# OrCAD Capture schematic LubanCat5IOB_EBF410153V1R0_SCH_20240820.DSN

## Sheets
1 17 MIPI DSI: size A4; title: 野火鲁班猫5.BTB底板; rev: V1.0; note: MIPI DSI接口; note: https://yehuosm.tmall.com
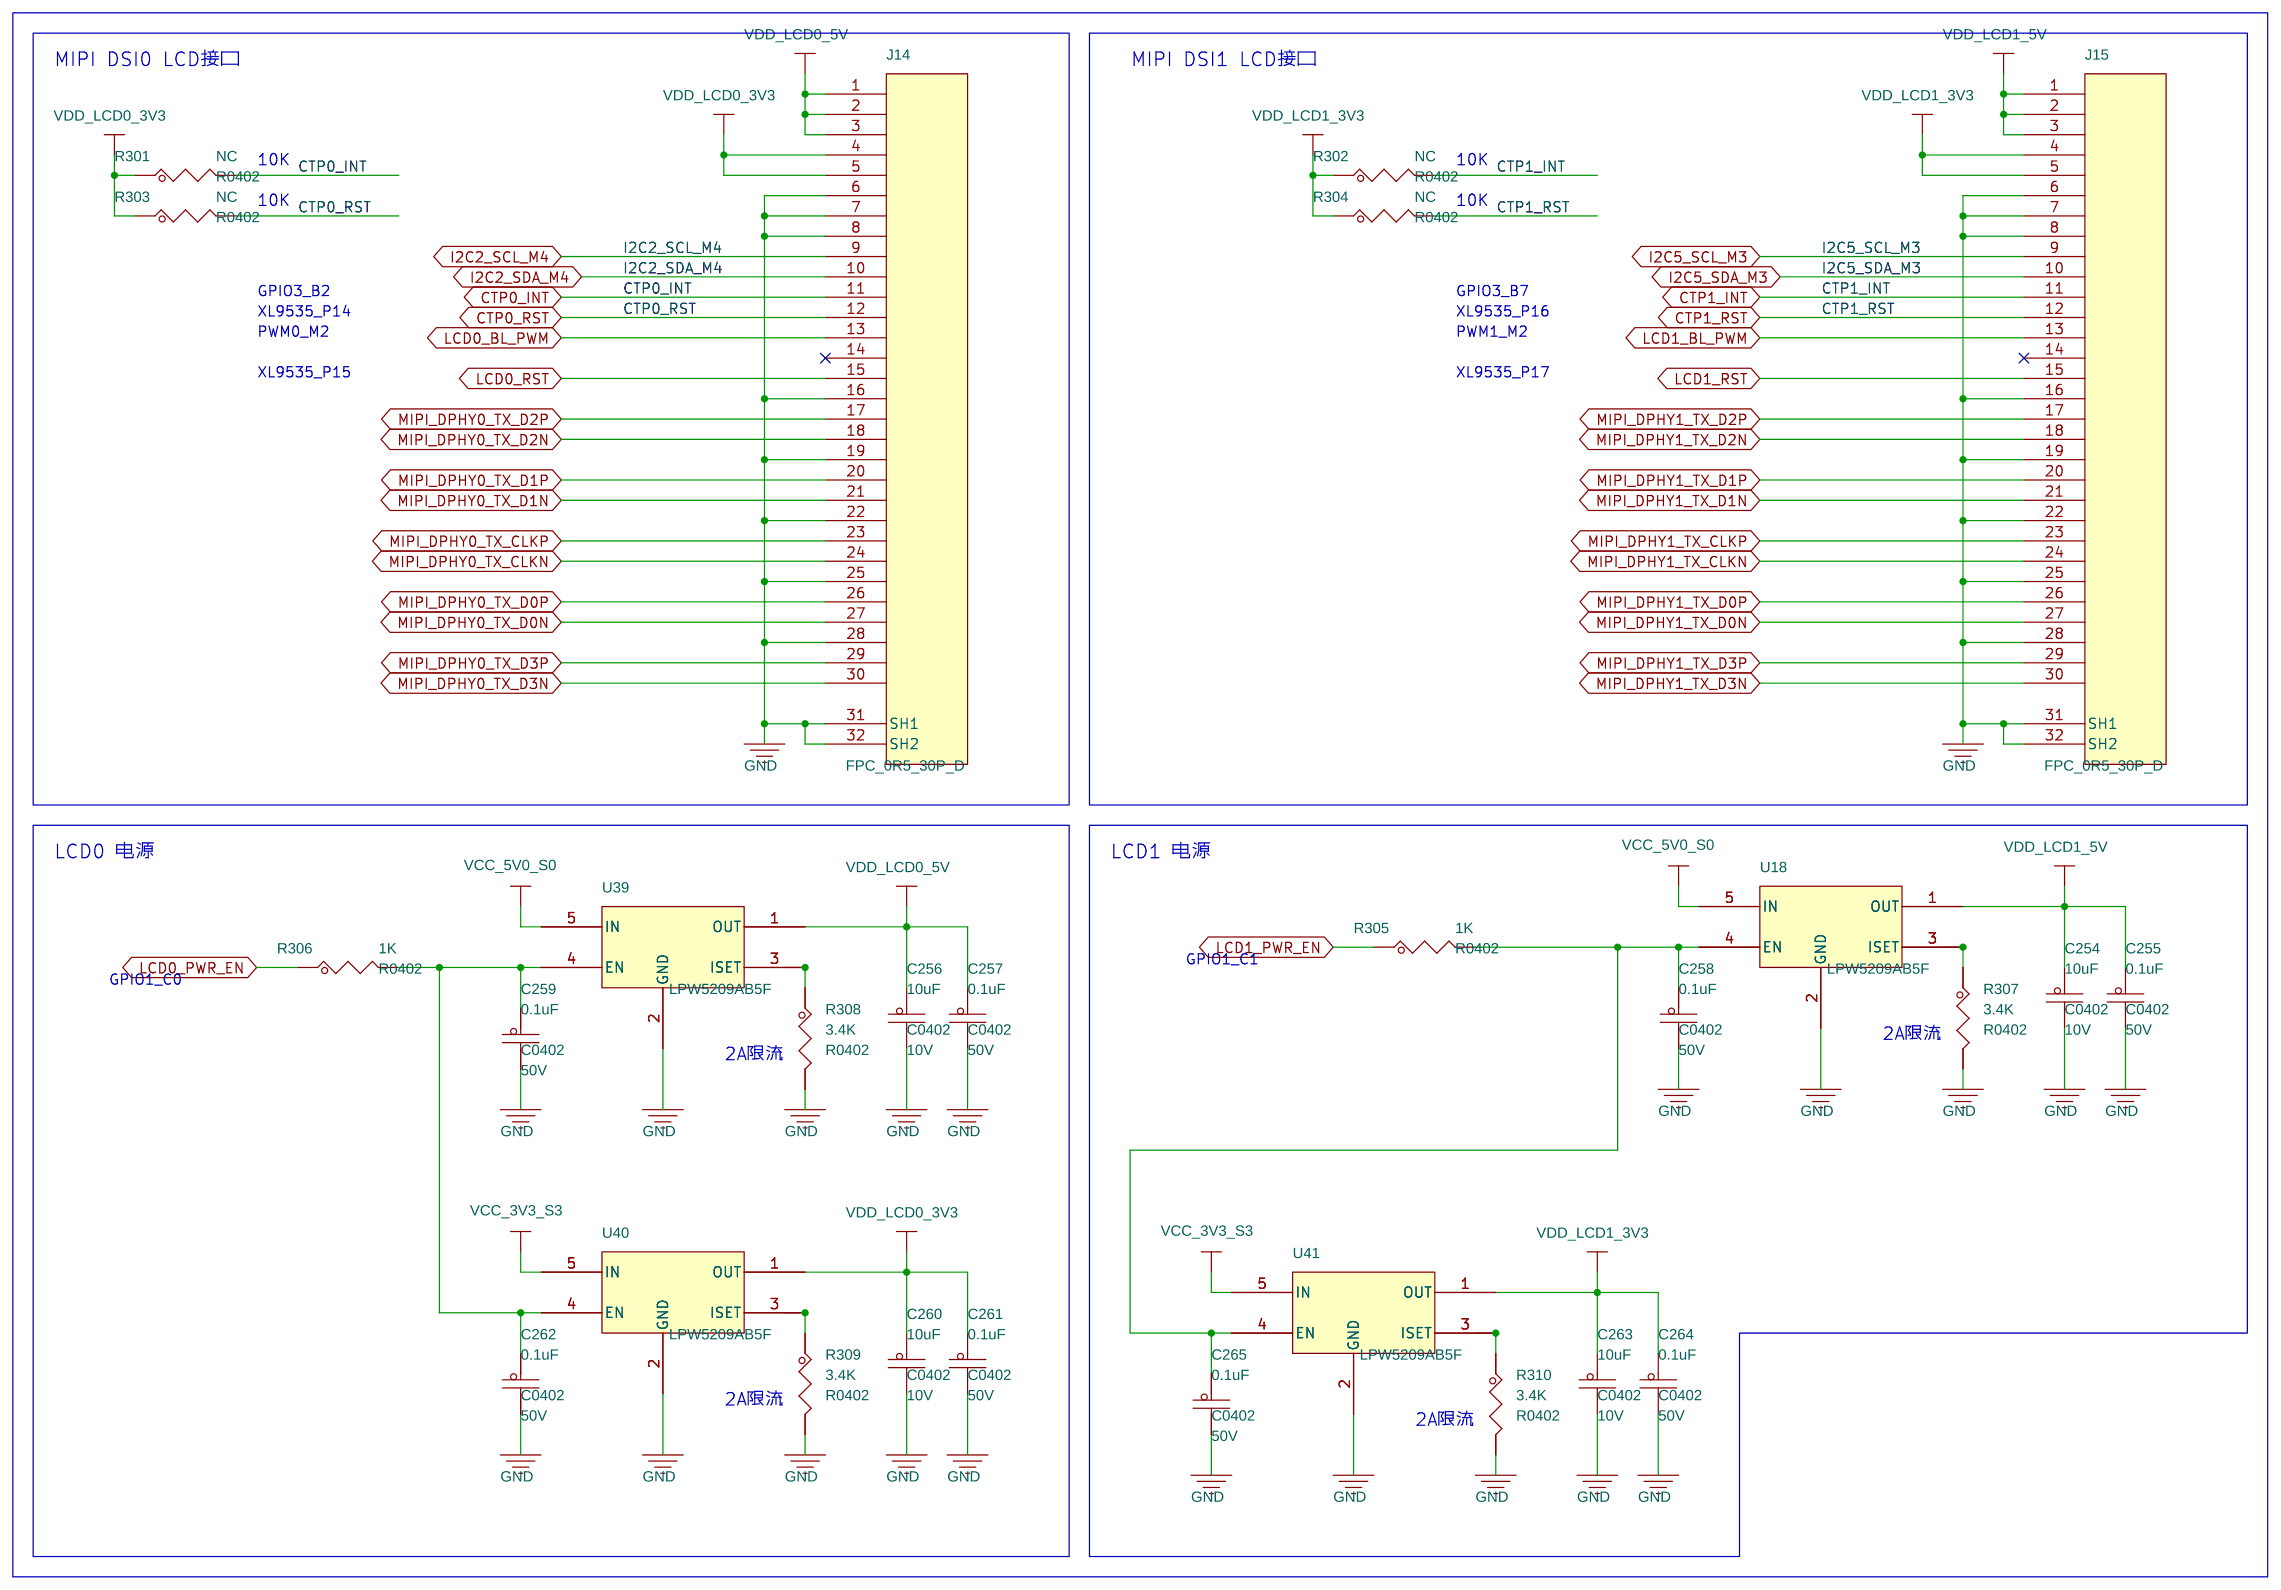
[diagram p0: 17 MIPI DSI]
2 06 RS232/RS485/CAN: size A4; note: RS232/RS485/CAN
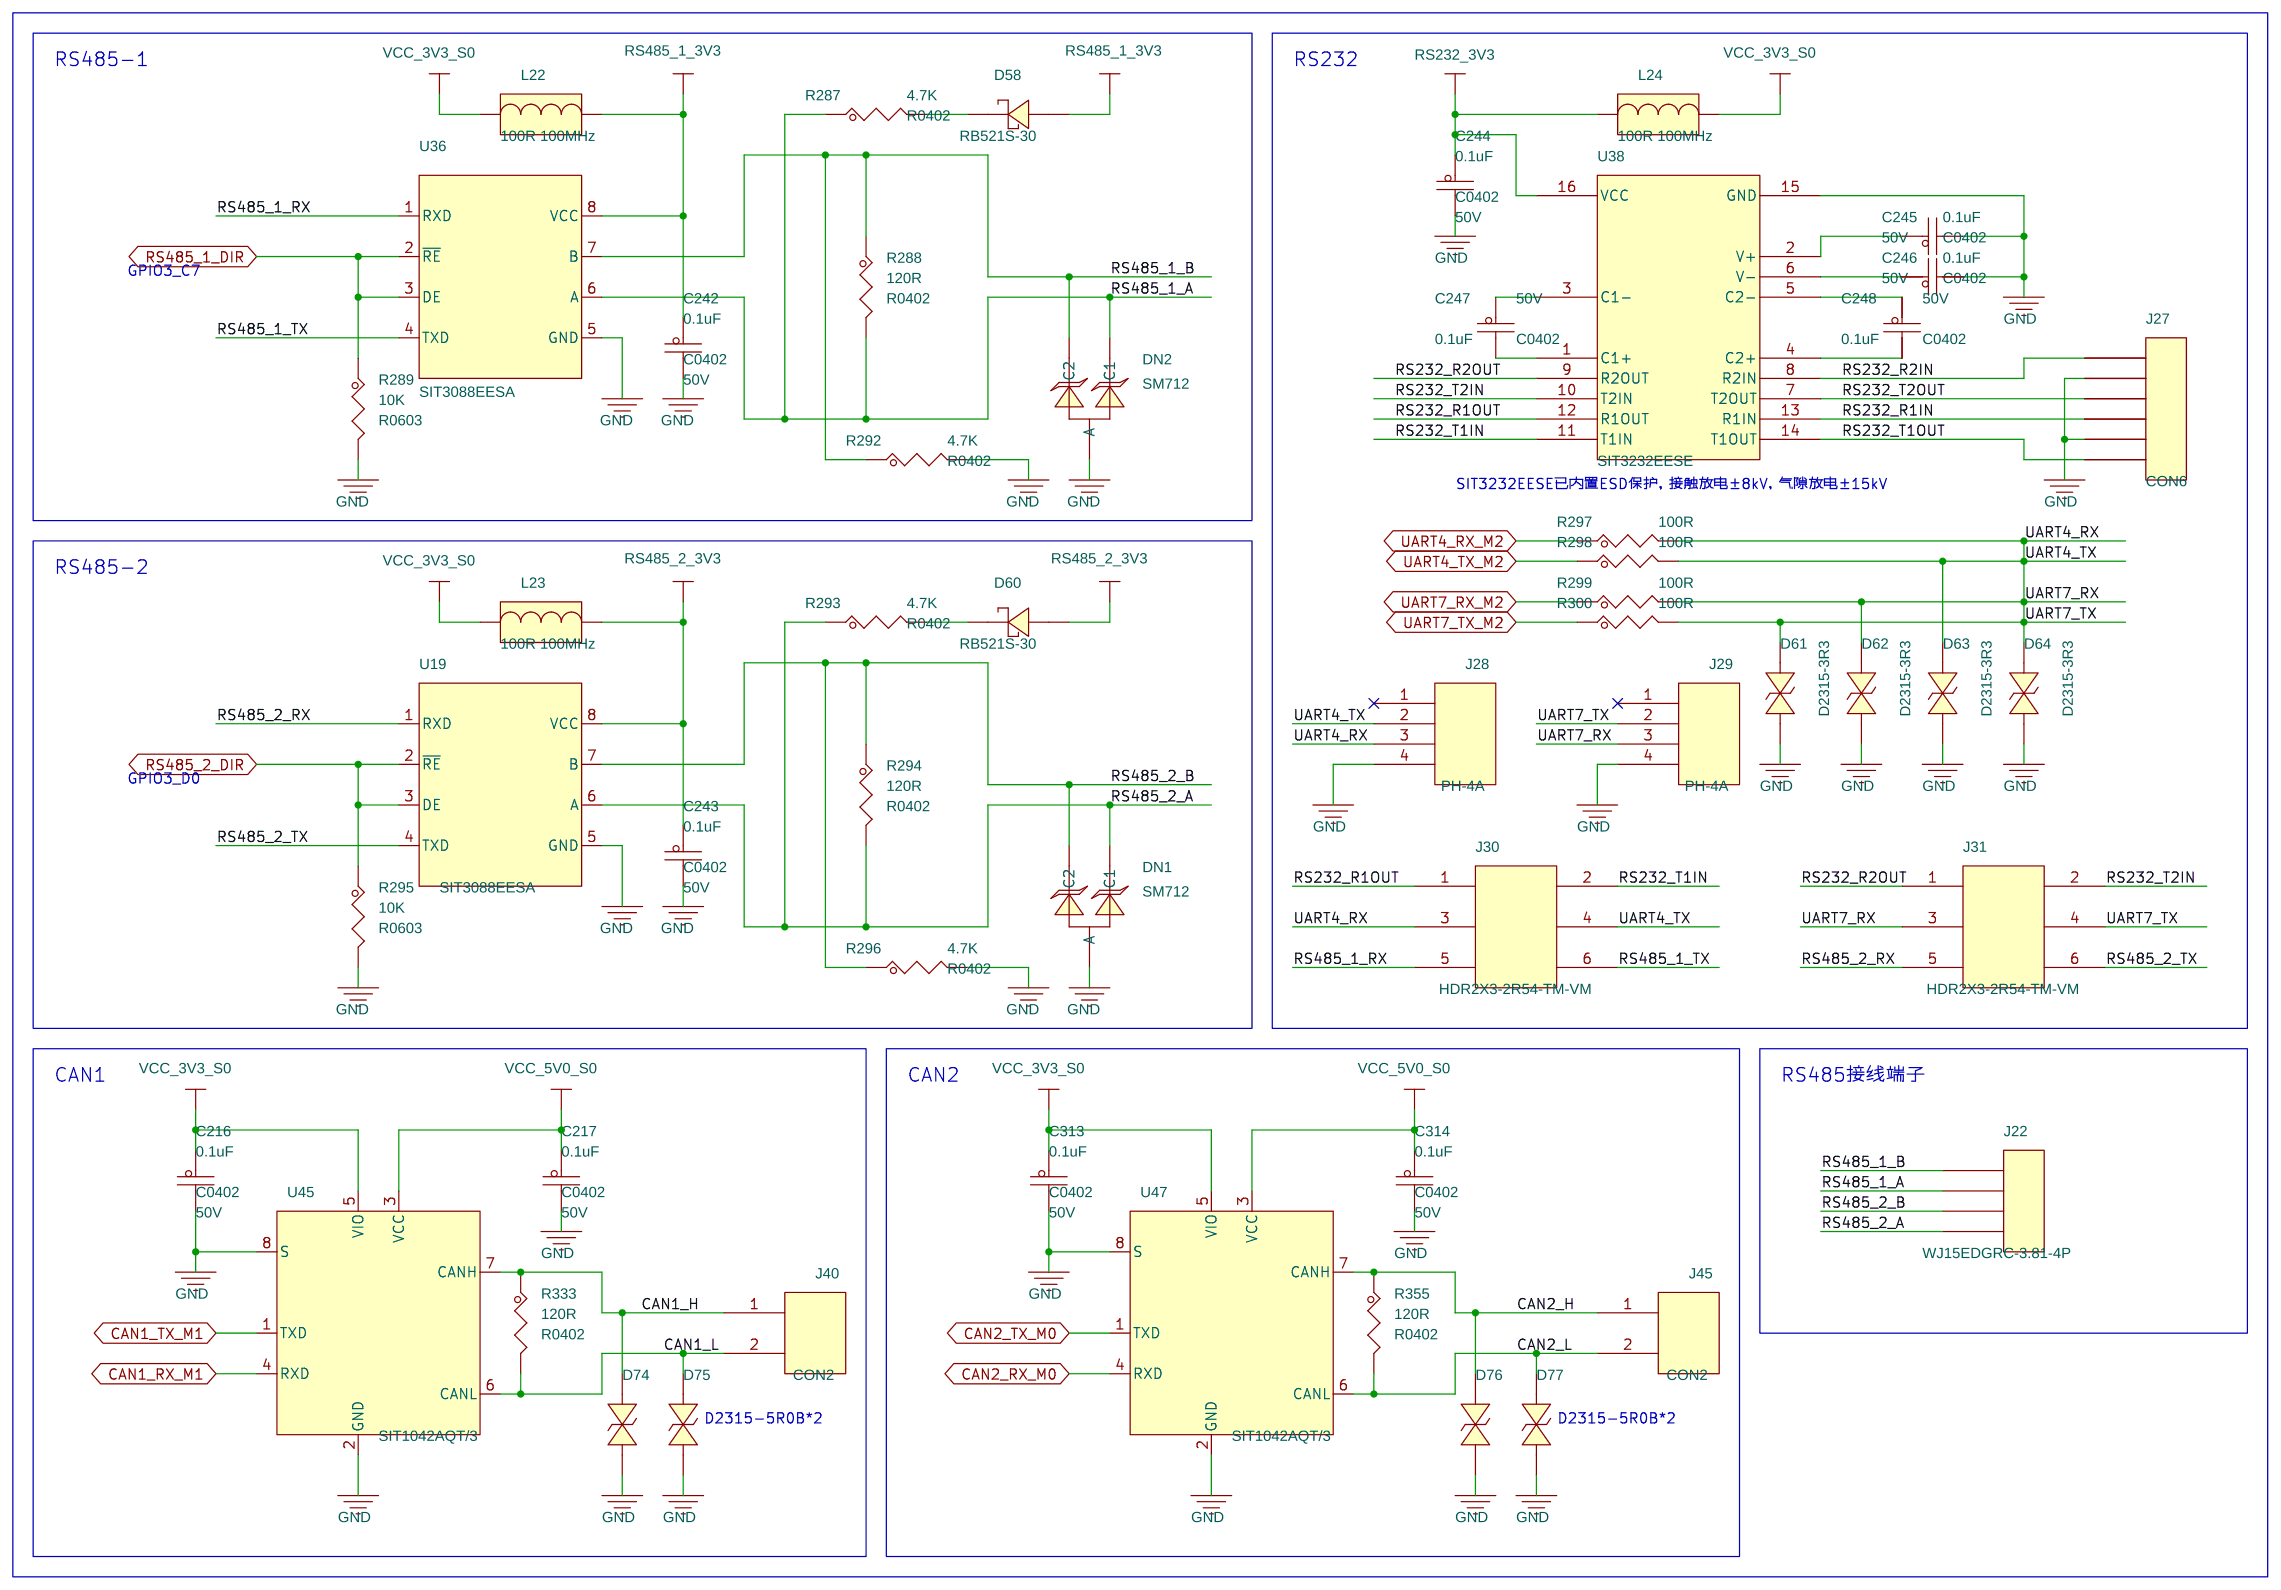
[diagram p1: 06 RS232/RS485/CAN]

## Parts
sheet 06 RS232/RS485/CAN
C216  0.1uF  [C0402]
C217  0.1uF  [C0402]
C242  0.1uF  [C0402]
C243  0.1uF  [C0402]
C244  0.1uF  [C0402]
C245  0.1uF  [C0402]
C246  0.1uF  [C0402]
C247  0.1uF  [C0402]
C248  0.1uF  [C0402]
C313  0.1uF  [C0402]
C314  0.1uF  [C0402]
D58  RB521S-30  [SOD523]
D60  RB521S-30  [SOD523]
D61  D2315-3R3  [esd0402]
D62  D2315-3R3  [esd0402]
D63  D2315-3R3  [esd0402]
D64  D2315-3R3  [esd0402]
D74  D2315-5R0B  [esd0402]
D75  D2315-5R0B  [esd0402]
D76  D2315-5R0B  [esd0402]
D77  D2315-5R0B  [esd0402]
DN1  SM712  [SOT23]
DN2  SM712  [SOT23]
J22  WJ15EDGRC-3.81-4P  [DB2ERC-3P81-4P]
J27  CON6  [DB2ERC-3P81-6P]
J28  PH-4A  [PH-1X4-2P0]
J29  PH-4A  [PH-1X4-2P0]
J30  HDR2X3-2R54-TM-VM  [HDR2X3-2R54-TM-VM]
J31  HDR2X3-2R54-TM-VM  [HDR2X3-2R54-TM-VM]
J40  CON2  [db2erc-3p81-2p]
J45  CON2  [db2erc-3p81-2p]
L22  100R 100MHz  [L0603]
L23  100R 100MHz  [L0603]
L24  100R 100MHz  [L0603]
R287  4.7K  [R0402]
R288  120R  [R0402]
R289  10K  [R0603]
R292  4.7K  [R0402]
R293  4.7K  [R0402]
R294  120R  [R0402]
R295  10K  [R0603]
R296  4.7K  [R0402]
R297  100R  [R0402]
R298  100R  [R0402]
R299  100R  [R0402]
R300  100R  [R0402]
R333  120R  [R0402]
R355  120R  [R0402]
U19  SIT3088EESA  [SOP8]
U36  SIT3088EESA  [SOP8]
U38  SIT3232EESE  [SOIC16]
U45  SIT1042AQT/3  [SOP8]
U47  SIT1042AQT/3  [SOP8]
sheet 17 MIPI DSI
C254  10uF  [C0402]
C255  0.1uF  [C0402]
C256  10uF  [C0402]
C257  0.1uF  [C0402]
C258  0.1uF  [C0402]
C259  0.1uF  [C0402]
C260  10uF  [C0402]
C261  0.1uF  [C0402]
C262  0.1uF  [C0402]
C263  10uF  [C0402]
C264  0.1uF  [C0402]
C265  0.1uF  [C0402]
J14  FPC_0R5_30P_D  [FPC-30P-0P5]
J15  FPC_0R5_30P_D  [FPC-30P-0P5]
R301  NC  [R0402]
R302  NC  [R0402]
R303  NC  [R0402]
R304  NC  [R0402]
R305  1K  [R0402]
R306  1K  [R0402]
R307  3.4K  [R0402]
R308  3.4K  [R0402]
R309  3.4K  [R0402]
R310  3.4K  [R0402]
U18  LPW5209AB5F  [SOT23-5]
U39  LPW5209AB5F  [SOT23-5]
U40  LPW5209AB5F  [SOT23-5]
U41  LPW5209AB5F  [SOT23-5]

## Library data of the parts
C216 C217 C242-C248 C255 C257-C259 C261 C262 C264 C265 C313 C314 = CAP_NP: Voltage: 50V; 规格: 贴片电容0.1uF 10% 50V X5R 0402; 规格编号: 0402X104K500NT; 规格书: 风华电容.pdf; 价格: 0.029826; 类别: 贴片电容0402; 品牌: 风华; 生命周期: 量产; 条码: EBF29060118
D58 D60 = DIODE_SCHTKY: 规格: 直流反向耐压(Vr)：30V 平均整流电流(Io)：200mA 正向压降(Vf)：500mV@200mA 30V@100mA,VF=350mV@10mA; 规格书: 江苏长电_RB521S-30.pdf; 价格: 0.06781; 类别: 贴片肖特基二极管; 品牌: 江苏长电; 生命周期: 量产; 条码: EBFCIS221114153437
D61-D64 = DIODE_BI-DIR_TRIG: 备注: 通用; 规格: 防静电保护ESD二极管 反向工作电压3.3V 击穿电压3.5V 钳位电压9V 结电容Cj 10pF; 规格书: 千虹_D2315-3R3.pdf; 类别: 贴片ESD; 品牌: 千虹; 生命周期: 量产; 条码: EBFCIS240517170749
D74-D77 = DIODE_BI-DIR_TRIG: 备注: 通用; 规格: 防静电保护ESD二极管 反向工作电压5V 击穿电压7V 钳位电压10.5V 结电容Cj 0.3pF; 规格书: 千虹_D2315-5R0B.pdf; 类别: 贴片ESD; 品牌: 千虹; 生命周期: 量产; 条码: EBFCIS240517170922
DN1 DN2 = TVS_Arr_ComA: 规格: 防静电保护ESD二极管 箝位电压12V -7V 击穿电压13.3V -7.5V; 规格书: 时科_SM712.pdf; 价格: 0.273512; 类别: 贴片ESD; 品牌: 时科; 生命周期: 量产; 条码: EBFCIS221015085507
J22 = CON4: 规格: 插拔式接线端子 间距3.81mm 90度弯针 4PIN; 规格书: 康奈克斯电气-绿色端子弯针插座.pdf; 价格: 0.198381; 类别: 绿色插拔式接线端子; 品牌: 康奈克斯电气; 生命周期: 量产; 条码: EBF29040009
J27 = CON6: 规格: 绿色插拔式接线端子 间距3.81mm 90度弯针 6PIN; 规格编号: WJ15EDGRC-3.81-6P; 规格书: 康奈克斯电气-绿色端子弯针插座.pdf; 价格: 0.301748; 类别: 绿色插拔式接线端子; 品牌: 康奈克斯电气; 生命周期: 量产; 条码: EBF29040013
J28 J29 = 1X4PIN: 规格: 直针PH2.0-4P 间距2.0MM 拔插式 接插件; 规格书: 博穆精密-PH2.0.pdf; 价格: 0.017; 可替代料: EBF29020025; 类别: PH连接器; 品牌: 博穆精密; 生命周期: 量产; 条码: EBF29020025
J30 J31 = 2X3PIN: 规格: 蓝色直插双排排针 总PIN数6 间距2.54mm; 规格编号: HDR2X3-2R54-TM-VM-BLUE; 规格书: 州日_双排针_直插_2P54.pdf; 类别: 2.54mm直插双排排针; 品牌: 州日; 生命周期: 量产; 条码: EBF29020030
J40 J45 = CON2: 规格: 绿色插拔式接线端子母座_2Pin  90度弯针 3.81间距; 规格编号: WJ15EDGRC-3.81-2P; 规格书: C8387_插针_板端弯针2P3.81MM_2019-12-25 .pdf; 价格: 0.107525; 类别: 绿色插拔式接线端子; 品牌: 康奈克斯电气; 生命周期: 量产; 条码: EBF29040070
L22-L24 = BEAD: 规格: 磁珠100Ω @100MHz 额定电流3A 直流电阻30mΩ; 规格编号: UPZ1608E101-3R0TF; 规格书: 顺络-磁珠.pdf; 价格: 0.021567; 类别: 贴片磁珠0603; 品牌: 顺络; 生命周期: 量产; 条码: EBF29050038
R287 R292 R293 R296 = RES: 规格: 贴片电阻4.7K 1% 1/16W 0402; 规格编号: RI0402L4701FT; 规格书: 合科泰-RI系列电阻.pdf; 类别: 贴片电阻0402; 品牌: 合科泰; 生命周期: 量产; 条码: EBF29070047
R288 R294 R333 R355 = RES: 规格: 贴片电阻120R 1% 1/16W 0402; 规格编号: 0402WGF1200TCE; 规格书: 厚声-无铅厚膜电阻.pdf; 价格: 0.002198; 类别: 贴片电阻0402; 品牌: 厚声; 生命周期: 量产; 条码: EBF29070275
R289 R295 = RES: 规格: 贴片电阻10K 1% 1/10W 0603; 规格编号: RI0603L1002FT; 规格书: 合科泰-RI系列电阻.pdf; 类别: 贴片电阻0603; 品牌: 合科泰; 生命周期: 量产; 条码: EBF29070074
R297-R300 = RES: 规格: 贴片电阻100R 1% 1/16W 0402; 规格编号: RI0402L1000FT; 规格书: 合科泰-RI系列电阻.pdf; 类别: 贴片电阻0402; 品牌: 合科泰; 生命周期: 量产; 条码: EBF29070053
U19 U36 = SIT3088E-8P: 备注: 鲁班猫; 规格: RS-485/RS-422芯片 收发器 允许256个器件连接总线 协议类别RS-485 电源电压3.0V~5.5V 数据速率14Mbps; 规格书: 芯力特_SIT3088E-V1.8_cn.pdf; 类别: RS485/RS422芯片; 品牌: 芯力特; 生命周期: 量产; 条码: EBFCIS231207153322
U38 = MAX3232CSE: 备注: 鲁班猫; 规格: RS232芯片 收发器 驱动器/接收器数：2/2 协议类别RS232 电源电压3.0V~5.5V 数据速率96kbps; 规格书: 芯力特_SIT3232E-V1.17-cn.pdf; 类别: RS232芯片; 品牌: 芯力特; 生命周期: 量产; 条码: EBFCIS231207155139
U45 U47 = TJA1057GT3_8P: 备注: 替代TJA1042T/3/1J; 规格: CAN芯片 收发器 驱动器/接收器数：1/1 协议类别CAN总线 电源电压4.5V~5.5V 数据速率5Mbps; 规格书: 芯力特_SIT1042.pdf; 价格: 1.98; 类别: CAN芯片; 品牌: 芯力特; 生命周期: 量产; 条码: EBFCIS230524153230
C254 C256 C260 C263 = CAP_NP: Voltage: 10V; 规格: 贴片电容10uF 20% 10V X5R 0402; 规格编号: CL05A106MP8NUB8; 规格书: 三星电容.pdf; 价格: 0.518415; 类别: 贴片电容0402; 品牌: 三星; 生命周期: 量产; 条码: EBF29060247
J14 J15 = FPC-30P: 规格: FPC连接器 针脚数30 间距0.5mm 高度2.0mm 下接 卧贴 翻盖式; 规格编号: FPC-05F-30PH20; 规格书: FPC-05F-NPH20.pdf; 类别: FPC连接器; 品牌: 讯普; 生命周期: 量产; 条码: EBF29040079
R301-R304 = RES: 规格: 贴片电阻NC 预留; 类别: 贴片电阻0402; 条码: EBF29070087
R305 R306 = RES: 规格: 贴片电阻1K 1% 1/16W 0402; 规格编号: RI0402L1001FT; 规格书: 合科泰-RI系列电阻.pdf; 类别: 贴片电阻0402; 品牌: 合科泰; 生命周期: 量产; 条码: EBF29070050
R307-R310 = RES: 规格: 贴片电阻3.4K 1% 1/16W 0402; 规格编号: RI0402L3401FT; 规格书: 合科泰-RI系列电阻.pdf; 类别: 贴片电阻0402; 品牌: 合科泰; 生命周期: 量产; 条码: EBF29070186
U18 U39-U41 = LPW5209AB5F: 规格: 集成电源开关 导通电阻：80mΩ 最大可设置保护电流：2.1A 输入电压：2.5V~6V 静态电流：30uA 其他功能：软启动、短路保护、热保护; 规格书: 微源半导体_LPW5209AB5F.pdf; 价格: 0.468063; 类别: 功率开关; 品牌: 微源半导体; 生命周期: 量产; 条码: EBF29280015

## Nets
GND: C216.2 C217.2 C242.2 C243.2 C244.2 C245.2 C246.2 C254.2 C255.2 C256.2 C257.2 C258.2 C259.2 C260.2 C261.2 C262.2 C263.2 C264.2 C265.2 C313.2 C314.2 D61.2 D62.2 D63.2 D64.2 D74.1 D75.1 D76.1 D77.1 DN1.3(A) DN2.3(A) J14.6 J14.7 J14.8 J14.16 J14.19 J14.22 J14.25 J14.28 J14.31(SH1) J14.32(SH2) J15.6 J15.7 J15.8 J15.16 J15.19 J15.22 J15.25 J15.28 J15.31(SH1) J15.32(SH2) J27.2 J27.5 J28.4 J29.4 R289.2 R292.2 R295.2 R296.2 R307.2 R308.2 R309.2 R310.2 U18.2(GND) U19.5(GND) U36.5(GND) U38.15(GND) U39.2(GND) U40.2(GND) U41.2(GND) U45.2(GND) U45.8(S) U47.2(GND) U47.8(S)
VCC_3V3_S0: C216.1 C313.1 L22.1 L23.1 L24.2 U45.5(VIO) U47.5(VIO)
VCC_3V3_S3: U40.5(IN) U41.5(IN)
VCC_5V0_S0: C217.1 C314.1 U18.5(IN) U39.5(IN) U45.3(VCC) U47.3(VCC)
VDD_LCD0_3V3: C260.1 C261.1 J14.4 J14.5 R301.1 R303.1 U40.1(OUT)
VDD_LCD0_5V: C256.1 C257.1 J14.1 J14.2 J14.3 U39.1(OUT)
VDD_LCD1_3V3: C263.1 C264.1 J15.4 J15.5 R302.1 R304.1 U41.1(OUT)
VDD_LCD1_5V: C254.1 C255.1 J15.1 J15.2 J15.3 U18.1(OUT)
CAN1_H: D74.2 J40.1 R333.1 U45.7(CANH)
CAN1_L: D75.2 J40.2 R333.2 U45.6(CANL)
CAN1_RX_M1: U45.4(RXD)
CAN1_TX_M1: U45.1(TXD)
CAN2_H: D76.2 J45.1 R355.1 U47.7(CANH)
CAN2_L: D77.2 J45.2 R355.2 U47.6(CANL)
CAN2_RX_M0: U47.4(RXD)
CAN2_TX_M0: U47.1(TXD)
CTP0_INT: J14.11 R301.2
CTP0_RST: J14.12 R303.2
CTP1_INT: J15.11 R302.2
CTP1_RST: J15.12 R304.2
I2C2_SCL_M4: J14.9
I2C2_SDA_M4: J14.10
I2C5_SCL_M3: J15.9
I2C5_SDA_M3: J15.10
LCD0_BL_PWM: J14.13
LCD0_PWR_EN: R306.1
LCD0_RST: J14.15
LCD1_BL_PWM: J15.13
LCD1_PWR_EN: R305.1
LCD1_RST: J15.15
MIPI_DPHY0_TX_CLKN: J14.24
MIPI_DPHY0_TX_CLKP: J14.23
MIPI_DPHY0_TX_D0N: J14.27
MIPI_DPHY0_TX_D0P: J14.26
MIPI_DPHY0_TX_D1N: J14.21
MIPI_DPHY0_TX_D1P: J14.20
MIPI_DPHY0_TX_D2N: J14.18
MIPI_DPHY0_TX_D2P: J14.17
MIPI_DPHY0_TX_D3N: J14.30
MIPI_DPHY0_TX_D3P: J14.29
MIPI_DPHY1_TX_CLKN: J15.24
MIPI_DPHY1_TX_CLKP: J15.23
MIPI_DPHY1_TX_D0N: J15.27
MIPI_DPHY1_TX_D0P: J15.26
MIPI_DPHY1_TX_D1N: J15.21
MIPI_DPHY1_TX_D1P: J15.20
MIPI_DPHY1_TX_D2N: J15.18
MIPI_DPHY1_TX_D2P: J15.17
MIPI_DPHY1_TX_D3N: J15.30
MIPI_DPHY1_TX_D3P: J15.29
RS232_3V3: C244.1 L24.1 U38.16(VCC)
RS232_R1IN: J27.4 U38.13(R1IN)
RS232_R1OUT: J30.1 U38.12(R1OUT)
RS232_R2IN: J27.1 U38.8(R2IN)
RS232_R2OUT: J31.1 U38.9(R2OUT)
RS232_T1IN: J30.2 U38.11(T1IN)
RS232_T1OUT: J27.6 U38.14(T1OUT)
RS232_T2IN: J31.2 U38.10(T2IN)
RS232_T2OUT: J27.3 U38.7(T2OUT)
RS485_1_3V3: C242.1 D58.2 L22.2 U36.8(VCC)
RS485_1_A: DN2.1(C1) J22.2 R287.1 R288.2 U36.6(A)
RS485_1_B: DN2.2(C2) J22.1 R288.1 R292.1 U36.7(B)
RS485_1_DIR: R289.1 U36.2(~{RE}) U36.3(DE)
RS485_1_RX: J30.5 U36.1(RXD)
RS485_1_TX: J30.6 U36.4(TXD)
RS485_2_3V3: C243.1 D60.2 L23.2 U19.8(VCC)
RS485_2_A: DN1.1(C1) J22.4 R293.1 R294.2 U19.6(A)
RS485_2_B: DN1.2(C2) J22.3 R294.1 R296.1 U19.7(B)
RS485_2_DIR: R295.1 U19.2(~{RE}) U19.3(DE)
RS485_2_RX: J31.5 U19.1(RXD)
RS485_2_TX: J31.6 U19.4(TXD)
UART4_RX: D64.1 J28.3 J30.3 R297.2
UART4_RX_M2: R297.1
UART4_TX: D63.1 J28.2 J30.4 R298.2
UART4_TX_M2: R298.1
UART7_RX: D62.1 J29.3 J31.3 R299.2
UART7_RX_M2: R299.1
UART7_TX: D61.1 J29.2 J31.4 R300.2
UART7_TX_M2: R300.1
N16921467: D58.1 R287.2
N16921931: D60.1 R293.2
N16922864: C247.1 U38.3(C1-)
N16922866: C247.2 U38.1(C1+)
N16922868: C248.1 U38.5(C2-)
N16922870: C248.2 U38.4(C2+)
N16922872: C246.1 U38.6(V-)
N16922874: C245.1 U38.2(V+)
N16966626: C259.1 C262.1 R306.2 U39.4(EN) U40.4(EN)
N16966707: C258.1 C265.1 R305.2 U18.4(EN) U41.4(EN)
N16966725: R307.1 U18.3(ISET)
N16966842: R310.1 U41.3(ISET)
N16967089: R308.1 U39.3(ISET)
N16967190: R309.1 U40.3(ISET)

Not connected (* = marked no-connect by the designer): J14 14*; J15 14*; J28 1*; J29 1*

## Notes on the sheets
sheet 1
- MIPI DSI0 LCD接口
- MIPI DSI1 LCD接口
- 10K
- 10K
- 10K
- 10K
- GPIO3_B2
- XL9535_P14
- GPIO3_B7
- XL9535_P16
- PWM0_M2
- PWM1_M2
- XL9535_P15
- XL9535_P17
- LCD0 电源
- LCD1 电源
- GPIO1_C1
- GPIO1_C0
- 2A限流
- 2A限流
- 2A限流
- 2A限流
sheet 2
- RS485-1
- RS232
- GPIO3_C7
- SIT3232EESE已内置ESD保护，接触放电±8kV，气隙放电±15kV
- RS485-2
- GPIO3_D0
- CAN1
- CAN2
- RS485接线端子
- D2315-5R0B*2
- D2315-5R0B*2
